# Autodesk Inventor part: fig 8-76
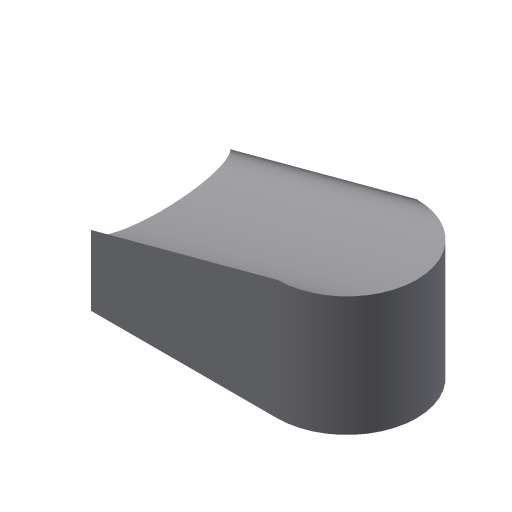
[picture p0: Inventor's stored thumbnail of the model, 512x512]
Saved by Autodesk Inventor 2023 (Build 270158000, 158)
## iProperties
Created: 2002-01
Part Number: fig 8-76
Document SubType Name: Modeling
Designer: ***
Density: 1 g/cm^3
Material: Generic
Appearance: Default
Control State: 0
Master: False
Checked Out: False
Shininess: 77.0
Length Units: 11269
Angle Units: 11279
Time Units: 11290
Mass Units: 11283
Length Display Precision: 3
Angle Display Precision: 2
Density: 0.0
Volumn: 0.0
Area: 0.0
PropertySet Name: Model Information
Author: ***
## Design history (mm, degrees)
sketch "Sketch2"
  geometry: L1 (-25.088, 14.941)-(-25.088, -14.161); L2 (-25.088, -14.161)-(13.729, -14.161); L3 (13.729, 14.941)-(-25.088, 14.941); A1 r 14.551 centre (13.729, 0.39) between (13.729, -14.161) and (13.729, 14.941)
  constraints: 6 end point, 2 point on circle, 2 tangent, 1 centre point, 1 parallel, 1 perpendicular, 1 vertical
extrude "Extrusion2" new body sketch "Sketch2" distance "d6" = 25; taper "d7" = 0 deg
feature "FaceDraft9" dims angle "d15" = 15 deg
body "Solid1"
